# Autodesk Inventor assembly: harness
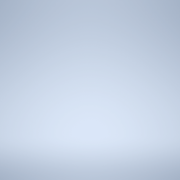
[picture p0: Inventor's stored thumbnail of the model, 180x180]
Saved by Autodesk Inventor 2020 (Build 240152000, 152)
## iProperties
Shininess: 64.0
Length Units: 11272
Angle Units: 11279
Time Units: 11290
Mass Units: 11286
Length Display Precision: 3
Angle Display Precision: 2
Compacted: True
HarnessSettings: <HarnessSettings><Defaults><Segments><Diameter value="0.200 in" fromwires="True"/><Offset value="0.100 in"/><ColorStyle value="Blue"/><BendRadius value="19" fro
Part Number: harness
Document SubType Name: Assembly
Created: 2002-07
Material: Générique
Density: 0.0
Volumn: 0.0
Area: 0.0
PropertySet Name: Model Information
Control State: 0
Master: False
Checked Out: False
HarnessSettings: <HarnessSettings><Defaults><Segments><Diameter value="0.200 in" fromwires="True"/><Offset value="0.100 in"/><ColorStyle value="Bleu - Peinture murale - Brillant
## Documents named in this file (1)
- C:\Users\Smoke\Desktop\far\harness.iam
